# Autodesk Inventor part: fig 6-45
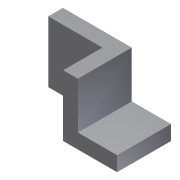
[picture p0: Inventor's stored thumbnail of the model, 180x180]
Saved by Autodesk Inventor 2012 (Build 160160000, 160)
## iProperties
Shininess: 77.0
Angle Display Precision: 2
Document Length Units: 11269
Document Angle Units: 11279
Document Time Units: 11290
Document Mass Units: 11283
Document Length Units Precision: 3
Document Angle Units Precision: 2
Created: 2001-12
Part Number: fig 6-45
Document SubType Name: Modeling
Designer: Renu Muthoo
Density: 1 g/cm^3
Material: Default
Density: 0.0
Volumn: 0.0
Area: 0.0
PropertySet Name: Model Information
Control State: 0
Master: False
Checked Out: False
Author: Renu Muthoo
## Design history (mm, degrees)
node "Sketch1"
sketch "Sketch2"
  geometry: L1 (16.794, 27.142)-(16.794, -22.858); L2 (16.794, -22.858)-(-27.206, -22.858); L3 (-27.206, -22.858)-(-27.206, -10.858); L4 (-27.206, -10.858)-(4.794, -10.858); L5 (4.794, -10.858)-(4.794, 27.142); L6 (4.794, 27.142)-(16.794, 27.142)
  constraints: 12 end point, 4 parallel, 2 perpendicular, 1 vertical
  dimensions: "d0" = 44 distance of L1.end L2.end; "d1" = 50 distance of L1.start L1.end; "d2" = 12 distance of L2.end L3.end
extrude "Extrusion1" new body sketch "Sketch2" distance "d3" = 44; taper "d4" = 0 deg
sketch "Sketch4"
  geometry: L1 (-16.794, -27.142)-(-16.794, 22.858) reference; L2 (27.206, 22.858)-(27.206, 10.858) reference; L3 (-16.794, -27.142)-(-61.001, -27.142); L4 (-61.001, -27.142)-(-61.001, 22.858); L5 (-61.001, 22.858)-(-16.794, 22.858)
  constraints: 6 end point, 2 perpendicular, 1 parallel
extrude "Extrusion3" join sketch "Sketch4" distance "d13" = 12; taper "d14" = 0 deg
body "Solid1"
